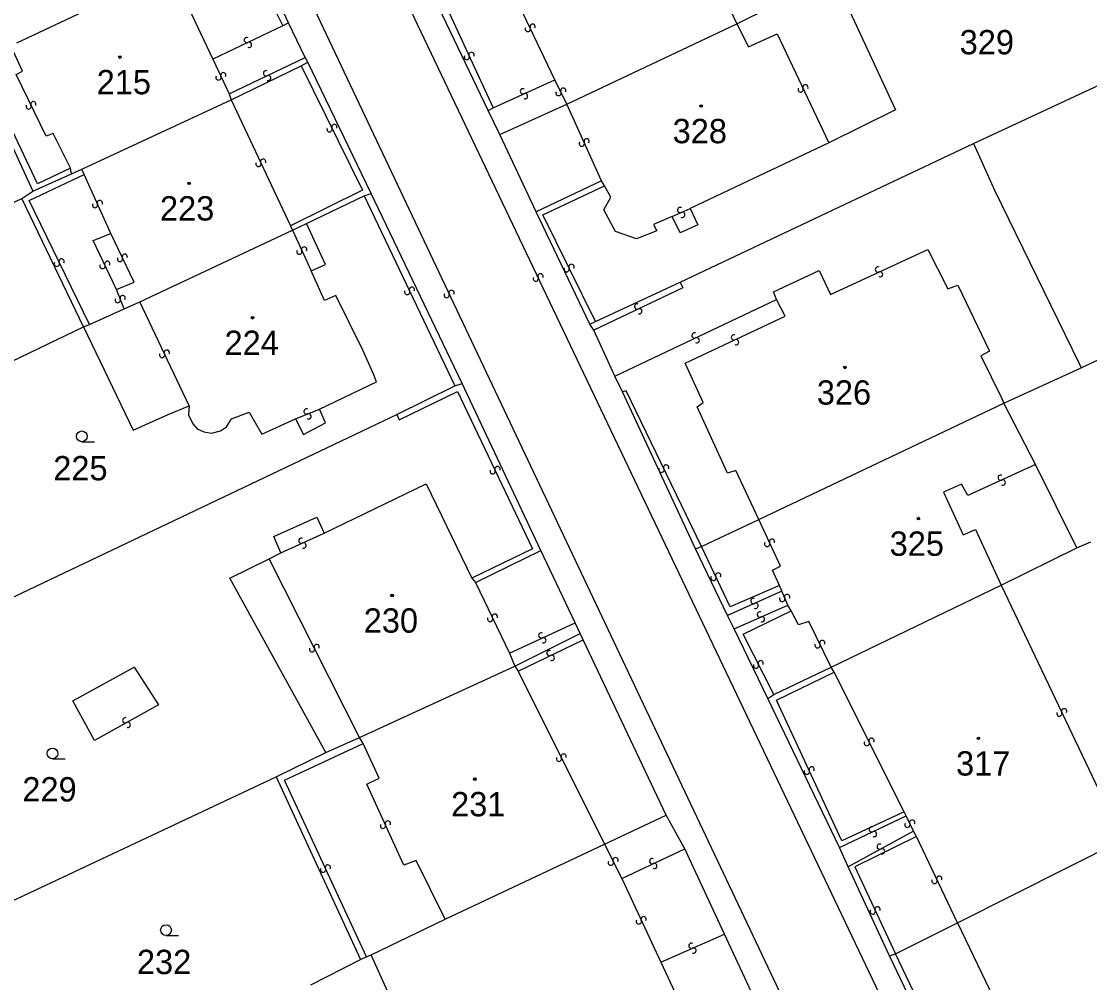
# Model space of a CAD drawing. Extents: x -600391 to -599491, y -1160176 to -1159402.
# Drawn here: x -600227.7 to -600153, y -1159801.1 to -1159733.9 of the extents above; entities that cross this region are included whole.
import ezdxf

# ---------------------------------------------------------------- set-up
doc = ezdxf.new("R2010")
doc.units = 0
for name, color, linetype in [('Level 1', 7, 'Continuous'), ('Level 13', 7, 'Continuous'), ('Level 3', 7, 'Continuous'), ('Level 4', 7, 'Continuous'), ('Level 5', 7, 'Continuous')]:
    doc.layers.add(name, color=color, linetype=linetype)

msp = doc.modelspace()

# ---------------------------------------------------------------- linework, layer by layer
at = {"layer": 'Level 1'}
for points in [[(-600208.99, -1159734.03), (-600211.94, -1159727.78)], [(-600227.96, -1159735.44), (-600217.22, -1159730.36)], [(-600171.01, -1159730.92), (-600170.82, -1159731.24), (-600169.15, -1159730.44), (-600168.52, -1159731.82), (-600170.09, -1159732.6), (-600166.61, -1159740.12), (-600171.26, -1159742.42)], [(-600195.05, -1159740.16), (-600198.5, -1159732.97)], [(-600177.67, -1159734.1), (-600175.23, -1159732.89)], [(-600207.83, -1159736.46), (-600208.99, -1159734.03)], [(-600189.55, -1159739.72), (-600177.67, -1159734.1)], [(-600161.16, -1159742.46), (-600146.3, -1159735.55)], [(-600207.65, -1159736.78), (-600207.83, -1159736.46)], [(-600230.94, -1159736.91), (-600226.86, -1159745.79)], [(-600213.01, -1159739.43), (-600208.1, -1159737.04)], [(-600208.1, -1159737.04), (-600207.65, -1159736.78)], [(-600203.22, -1159745.95), (-600207.65, -1159736.78)], [(-600223.43, -1159744.26), (-600213.01, -1159739.43)], [(-600194.23, -1159741.85), (-600195.05, -1159740.16)], [(-600194.23, -1159741.85), (-600189.55, -1159739.72)], [(-600191.69, -1159747.24), (-600194.23, -1159741.85)], [(-600181.63, -1159752.15), (-600161.16, -1159742.46)], [(-600171.26, -1159742.42), (-600180.94, -1159747)], [(-600161.16, -1159742.46), (-600159.69, -1159745.74), (-600153.77, -1159757.84), (-600153.64, -1159758.15)], [(-600226.86, -1159745.79), (-600224.16, -1159744.58)], [(-600224.16, -1159744.58), (-600223.43, -1159744.26)], [(-600187.13, -1159745.08), (-600191.69, -1159747.24)], [(-600186.92, -1159745.43), (-600187.13, -1159745.08)], [(-600182.2, -1159747.56), (-600183.5, -1159748.12), (-600183.27, -1159748.58), (-600184.69, -1159749.12), (-600186.16, -1159748.61), (-600186.98, -1159747.11), (-600186.48, -1159746.21), (-600186.92, -1159745.43)], [(-600227.63, -1159746.31), (-600226.86, -1159745.79)], [(-600207.73, -1159748.06), (-600203.71, -1159746.12)], [(-600203.71, -1159746.12), (-600203.22, -1159745.95)], [(-600196.87, -1159759.24), (-600203.22, -1159745.95)], [(-600251.26, -1159757.45), (-600227.63, -1159746.31)], [(-600223.31, -1159755.28), (-600227.63, -1159746.31)], [(-600187.96, -1159755.09), (-600191.69, -1159747.24)], [(-600180.94, -1159747), (-600180.41, -1159748.14), (-600181.63, -1159748.71), (-600182.2, -1159747.56)], [(-600208.72, -1159748.53), (-600207.73, -1159748.06)], [(-600207.42, -1159751.37), (-600206.42, -1159750.91), (-600207.73, -1159748.06)], [(-600219.39, -1159753.54), (-600208.72, -1159748.53)], [(-600206.84, -1159761.02), (-600202.85, -1159759.11), (-600203.04, -1159758.62), (-600203.78, -1159756.95), (-600205.68, -1159753.09), (-600206.48, -1159753.43), (-600207.42, -1159751.37)], [(-600153.64, -1159758.15), (-600138, -1159750.77)], [(-600187.56, -1159754.91), (-600181.63, -1159752.15)], [(-600220.48, -1159754.01), (-600219.39, -1159753.54)], [(-600222.9, -1159755.12), (-600220.48, -1159754.01)], [(-600223.31, -1159755.28), (-600222.9, -1159755.12)], [(-600187.96, -1159755.09), (-600187.56, -1159754.91)], [(-600187.68, -1159755.5), (-600187.96, -1159755.09)], [(-600246.59, -1159766.48), (-600223.31, -1159755.28)], [(-600223.31, -1159755.28), (-600219.85, -1159762.49), (-600217.41, -1159761.4), (-600215.93, -1159760.79)], [(-600186.2, -1159758.73), (-600187.68, -1159755.5)], [(-600185.67, -1159759.81), (-600186.2, -1159758.73)], [(-600159.03, -1159760.61), (-600153.64, -1159758.15)], [(-600201.43, -1159761.41), (-600197.38, -1159759.4)], [(-600197.38, -1159759.4), (-600196.87, -1159759.24)], [(-600191.36, -1159770.9), (-600196.87, -1159759.24)], [(-600180.56, -1159770.78), (-600185.67, -1159759.81)], [(-600215.93, -1159760.79), (-600215.97, -1159761.42), (-600215.67, -1159762.05), (-600215.37, -1159762.39), (-600214.9, -1159762.61), (-600214.38, -1159762.7), (-600213.75, -1159762.55), (-600213.33, -1159762.25), (-600212.97, -1159761.71), (-600211.75, -1159761.23), (-600210.85, -1159762.78), (-600208.5, -1159761.69)], [(-600208.5, -1159761.69), (-600207.94, -1159762.79), (-600206.4, -1159761.99), (-600206.84, -1159761.02)], [(-600176.14, -1159768.74), (-600159.03, -1159760.61)], [(-600156.81, -1159764.9), (-600159.03, -1159760.61)], [(-600239.75, -1159779.63), (-600201.43, -1159761.41)], [(-600153.94, -1159770.71), (-600156.81, -1159764.9)], [(-600206.51, -1159769.68), (-600199.39, -1159766.24), (-600196.2, -1159772.82)], [(-600209.53, -1159771.07), (-600210.02, -1159769.92), (-600207.02, -1159768.56), (-600206.51, -1159769.68)], [(-600180.16, -1159770.62), (-600176.14, -1159768.74)], [(-600180.56, -1159770.78), (-600180.16, -1159770.62)], [(-600178.34, -1159775.45), (-600180.56, -1159770.78)], [(-600159.23, -1159773.32), (-600153.94, -1159770.71)], [(-600153.94, -1159770.71), (-600152.96, -1159770.3)], [(-600206.39, -1159785), (-600213.09, -1159772.84), (-600210.34, -1159771.48)], [(-600210.34, -1159771.48), (-600209.53, -1159771.07)], [(-600195.93, -1159773.14), (-600191.36, -1159770.9)], [(-600188.97, -1159775.94), (-600191.36, -1159770.9)], [(-600196.2, -1159772.82), (-600195.93, -1159773.14)], [(-600171.1, -1159779.04), (-600159.23, -1159773.32)], [(-600188.62, -1159776.69), (-600188.97, -1159775.94)], [(-600177.86, -1159776.38), (-600178.34, -1159775.45)], [(-600193.19, -1159778.98), (-600188.62, -1159776.69)], [(-600188.41, -1159777.13), (-600188.62, -1159776.69)], [(-600175.52, -1159781.23), (-600177.86, -1159776.38)], [(-600182.61, -1159789.39), (-600188.41, -1159777.13)], [(-600204.03, -1159783.96), (-600193.19, -1159778.98)], [(-600175.1, -1159780.96), (-600171.1, -1159779.04)], [(-600175.52, -1159781.23), (-600175.1, -1159780.96)], [(-600170.5, -1159791.65), (-600175.52, -1159781.23)], [(-600206.39, -1159785), (-600204.03, -1159783.96)], [(-600209.86, -1159786.71), (-600206.39, -1159785)], [(-600231.06, -1159796.68), (-600209.86, -1159786.71)], [(-600209.86, -1159786.71), (-600203.96, -1159799.47)], [(-600186.92, -1159791.42), (-600182.61, -1159789.39)], [(-600181.31, -1159791.73), (-600182.61, -1159789.39)], [(-600198.05, -1159796.66), (-600186.92, -1159791.42)], [(-600169.9, -1159792.99), (-600170.5, -1159791.65)], [(-600162.28, -1159796.91), (-600150.75, -1159791.1)], [(-600178.55, -1159797.71), (-600181.31, -1159791.73)], [(-600167.03, -1159799.22), (-600169.9, -1159792.99)], [(-600203.22, -1159799.15), (-600198.05, -1159796.66)], [(-600166.61, -1159799.07), (-600162.28, -1159796.91)], [(-600162.28, -1159796.91), (-600156.73, -1159808.45), (-600157.7, -1159809.01), (-600154.94, -1159814.73), (-600143.87, -1159808.62)], [(-600175.73, -1159803.75), (-600178.55, -1159797.71)], [(-600203.54, -1159799.29), (-600203.22, -1159799.15)], [(-600167.03, -1159799.22), (-600166.61, -1159799.07)], [(-600207.44, -1159801.23), (-600203.96, -1159799.47)], [(-600203.96, -1159799.47), (-600203.54, -1159799.29)], [(-600156.4, -1159821.41), (-600167.03, -1159799.22)]]:
    msp.add_lwpolyline(points, dxfattribs=at)
at = {"layer": 'Level 13'}
for centre, start, end in [((-600191.943, -1159734.312), 332.57245, 205.16245), ((-600192.277, -1159734.468), 152.78691, 24.88491), ((-600211.908, -1159735.243), 62.4944, 295.0844), ((-600211.753, -1159735.577), 242.70886, 114.80685), ((-600196.547, -1159736.437), 152.01879, 24.60879), ((-600196.212, -1159736.284), 332.23325, 204.33124), ((-600213.887, -1159737.857), 152.18813, 24.77813), ((-600213.552, -1159737.704), 332.40259, 204.50058), ((-600210.568, -1159737.563), 62.80681, 294.90481), ((-600210.412, -1159737.897), 242.59235, 115.18235), ((-600192.625, -1159738.821), 61.8267, 293.9247), ((-600189.804, -1159738.78), 333.31984, 205.90984), ((-600173.227, -1159738.698), 152.47532, 25.06532), ((-600172.893, -1159738.543), 332.68978, 204.78777), ((-600192.475, -1159739.158), 241.61225, 114.20225), ((-600190.136, -1159738.94), 153.5343, 25.6323), ((-600227.147, -1159739.879), 153.29464, 25.39264), ((-600226.814, -1159739.72), 333.08019, 205.67019), ((-600206.126, -1159741.47), 153.30029, 25.89029), ((-600205.794, -1159741.31), 333.51475, 205.61275), ((-600188.509, -1159742.474), 151.67155, 23.76955), ((-600188.172, -1159742.325), 331.4571, 204.0471), ((-600211.097, -1159743.898), 152.48484, 25.07484), ((-600210.763, -1159743.743), 332.69929, 204.79729), ((-600222.509, -1159746.774), 151.50234, 23.60034), ((-600222.172, -1159746.625), 331.28788, 203.87788), ((-600181.643, -1159747.111), 61.33522, 293.43322), ((-600181.496, -1159747.449), 241.12077, 113.71077), ((-600208.238, -1159750.026), 151.75405, 24.34405), ((-600207.902, -1159749.875), 331.96851, 204.0665), ((-600224.844, -1159750.71), 333.11213, 205.70213), ((-600220.767, -1159750.538), 152.98634, 25.08434), ((-600220.434, -1159750.381), 332.77189, 205.36189), ((-600225.177, -1159750.869), 153.32658, 25.42458), ((-600221.988, -1159751.027), 152.58193, 24.67992), ((-600221.653, -1159750.872), 332.36747, 204.95747), ((-600189.566, -1159751.25), 153.53755, 25.63555), ((-600189.234, -1159751.09), 333.3231, 205.9131), ((-600167.826, -1159751.272), 62.15856, 294.25656), ((-600167.674, -1159751.607), 241.9441, 114.5341), ((-600191.727, -1159751.908), 152.84713, 24.94513), ((-600191.393, -1159751.752), 332.63268, 205.22268), ((-600200.706, -1159752.838), 152.64339, 25.23339), ((-600200.373, -1159752.682), 332.85785, 204.95584), ((-600197.613, -1159752.903), 332.70521, 204.80321), ((-600220.922, -1159753.407), 149.17414, 21.27214), ((-600220.579, -1159753.272), 328.95969, 201.54969), ((-600197.947, -1159753.058), 152.49075, 25.08075), ((-600184.648, -1159753.853), 62.49655, 295.08655), ((-600184.493, -1159754.187), 242.711, 114.809), ((-600180.638, -1159755.883), 62.76906, 294.86706), ((-600177.887, -1159756.012), 62.44345, 294.54145), ((-600180.482, -1159756.217), 242.55461, 115.14461), ((-600177.733, -1159756.347), 242.22899, 114.81899), ((-600217.827, -1159757.238), 152.88514, 24.98314), ((-600217.494, -1159757.081), 332.67069, 205.26069), ((-600207.737, -1159761.188), 59.35245, 291.45045), ((-600207.602, -1159761.531), 239.13799, 111.72799), ((-600194.736, -1159765.368), 152.64995, 25.23995), ((-600194.403, -1159765.212), 332.8644, 204.9624), ((-600182.947, -1159765.259), 153.13175, 25.22975), ((-600182.614, -1159765.101), 332.91729, 205.50729), ((-600159.256, -1159765.812), 61.65685, 294.24685), ((-600159.105, -1159766.149), 241.87131, 113.96931), ((-600208.096, -1159770.212), 62.08769, 294.18569), ((-600207.944, -1159770.548), 241.87323, 114.46323), ((-600175.558, -1159770.436), 152.14787, 24.24587), ((-600175.223, -1159770.284), 331.93342, 204.52342), ((-600179.317, -1159772.808), 152.95191, 25.04991), ((-600178.984, -1159772.651), 332.73746, 205.32746), ((-600176.525, -1159774.422), 61.56805, 294.15805), ((-600174.51, -1159774.291), 150.57133, 22.66932), ((-600174.171, -1159774.148), 330.35687, 202.94687), ((-600176.375, -1159774.759), 241.78251, 113.88051), ((-600176.074, -1159775.371), 61.49181, 293.5898), ((-600194.916, -1159775.679), 152.7388, 25.3288), ((-600194.583, -1159775.522), 332.95326, 205.05125), ((-600175.926, -1159775.708), 241.27735, 113.86735), ((-600191.346, -1159776.832), 62.21892, 294.31692), ((-600207.025, -1159777.638), 333.97985, 206.56985), ((-600191.193, -1159777.167), 242.00447, 114.59447), ((-600172.047, -1159777.519), 153.28754, 25.38554), ((-600171.714, -1159777.36), 333.07309, 205.66309), ((-600207.355, -1159777.802), 154.1943, 26.2923), ((-600190.768, -1159778.063), 63.07511, 295.17311), ((-600190.611, -1159778.396), 242.86066, 115.45066), ((-600176.345, -1159778.942), 154.42563, 26.52363), ((-600176.016, -1159778.777), 334.21117, 206.80117), ((-600154.823, -1159782.132), 332.87109, 204.96909), ((-600220.399, -1159782.759), 66.18022, 298.77022), ((-600155.156, -1159782.289), 152.65664, 25.24664), ((-600220.222, -1159783.082), 246.39468, 118.49268), ((-600168.275, -1159784.188), 333.81718, 206.40718), ((-600168.606, -1159784.351), 154.03164, 26.12963), ((-600190.105, -1159785.451), 153.68544, 26.27544), ((-600189.774, -1159785.289), 333.89989, 205.99789), ((-600172.788, -1159786.346), 152.21068, 24.30868), ((-600172.453, -1159786.193), 331.99622, 204.58622), ((-600202.399, -1159790.125), 151.87767, 23.97567), ((-600202.062, -1159789.974), 331.66322, 204.25322), ((-600168.258, -1159790.373), 62.79302, 294.89101), ((-600165.767, -1159790.058), 152.85686, 24.95486), ((-600165.434, -1159789.902), 332.64241, 205.23241), ((-600168.102, -1159790.707), 242.57856, 115.16856), ((-600167.707, -1159791.588), 65.69826, 298.28826), ((-600186.154, -1159792.539), 334.0336, 206.13159), ((-600183.597, -1159792.602), 62.62389, 294.72189), ((-600167.533, -1159791.913), 245.91272, 118.01072), ((-600206.578, -1159793.196), 152.31841, 24.41641), ((-600206.243, -1159793.043), 332.10396, 204.69396), ((-600186.485, -1159792.702), 153.81914, 26.40914), ((-600183.442, -1159792.937), 242.40944, 114.99944), ((-600163.877, -1159793.977), 152.66988, 24.76787), ((-600163.543, -1159793.822), 332.45542, 205.04542), ((-600168.187, -1159796.117), 152.07691, 24.66691), ((-600167.852, -1159795.964), 332.29137, 204.38936), ((-600184.527, -1159796.807), 152.09469, 24.68469), ((-600184.192, -1159796.654), 332.30915, 204.40714), ((-600180.852, -1159798.51), 61.03588, 293.13387), ((-600180.707, -1159798.849), 240.82142, 113.41142)]:
    msp.add_arc(centre, 0.184, start, end, dxfattribs=at)
at = {"layer": 'Level 3'}
for points in [[(-600154.85, -1159824.6), (-600155.7, -1159824.37), (-600156.33, -1159824.07), (-600156.83, -1159823.72), (-600157.25, -1159823.34), (-600157.63, -1159822.87), (-600158.01, -1159822.25), (-600225.11, -1159681.41), (-600225.5, -1159680.26), (-600225.71, -1159678.98), (-600225.76, -1159677.2), (-600225.55, -1159675.64)], [(-600236.3, -1159676.88), (-600235.69, -1159677.1), (-600234.79, -1159677.54), (-600233.86, -1159678.21), (-600233.01, -1159679.1), (-600232.25, -1159680.16), (-600163.31, -1159825.79), (-600162.94, -1159826.86), (-600162.86, -1159827.88), (-600163.01, -1159828.81), (-600163.4, -1159829.75)], [(-600183.7, -1159725.92), (-600181.9, -1159729.68), (-600180.2, -1159728.82), (-600177.67, -1159734.1)], [(-600212.49, -1159728.03), (-600209.38, -1159734.25)], [(-600217.22, -1159730.36), (-600214.28, -1159736.57)], [(-600190.39, -1159738.01), (-600193.83, -1159730.77)], [(-600198.05, -1159732.74), (-600194.7, -1159739.97)], [(-600209.38, -1159734.25), (-600214.28, -1159736.57)], [(-600208.99, -1159734.03), (-600209.38, -1159734.25)], [(-600177.67, -1159734.1), (-600176.87, -1159735.72), (-600174.86, -1159734.81), (-600171.26, -1159742.42)], [(-600224.23, -1159744.2), (-600225.44, -1159741.77), (-600225.93, -1159741.95), (-600228.02, -1159737.65), (-600227.57, -1159737.41), (-600228.36, -1159735.69)], [(-600213.15, -1159738.99), (-600207.83, -1159736.46)], [(-600224.23, -1159744.2), (-600226.52, -1159745.29), (-600230.58, -1159736.74)], [(-600214.28, -1159736.57), (-600213.15, -1159738.99)], [(-600208.1, -1159737.04), (-600203.83, -1159745.74), (-600208.85, -1159748.22)], [(-600194.7, -1159739.97), (-600190.39, -1159738.01)], [(-600189.55, -1159739.72), (-600190.39, -1159738.01)], [(-600213.15, -1159738.99), (-600213.01, -1159739.43)], [(-600213.01, -1159739.43), (-600208.85, -1159748.22)], [(-600195.05, -1159740.16), (-600194.7, -1159739.97)], [(-600187.13, -1159745.08), (-600189.55, -1159739.72)], [(-600222.9, -1159755.12), (-600227.12, -1159746.45), (-600223.26, -1159744.63)], [(-600224.16, -1159744.58), (-600224.23, -1159744.2)], [(-600223.26, -1159744.63), (-600223.43, -1159744.26)], [(-600221.41, -1159748.76), (-600223.26, -1159744.63)], [(-600187.56, -1159754.91), (-600191.23, -1159747.44), (-600186.92, -1159745.43)], [(-600203.71, -1159746.12), (-600197.38, -1159759.4)], [(-600182.2, -1159747.56), (-600180.94, -1159747)], [(-600208.85, -1159748.22), (-600208.72, -1159748.53)], [(-600221.02, -1159752.66), (-600222.63, -1159749.24), (-600221.41, -1159748.76)], [(-600221.02, -1159752.66), (-600219.78, -1159752.16), (-600221.41, -1159748.76)], [(-600208.72, -1159748.53), (-600207.42, -1159751.37)], [(-600174.91, -1159753.37), (-600175.13, -1159752.84), (-600171.94, -1159751.34), (-600171.15, -1159753.01), (-600164.35, -1159749.87), (-600162.94, -1159752.61), (-600162.24, -1159752.36), (-600160.03, -1159756.98), (-600160.65, -1159757.29), (-600159.17, -1159760.27), (-600159.03, -1159760.61)], [(-600181.63, -1159752.15), (-600181.45, -1159752.55), (-600187.68, -1159755.5)], [(-600220.48, -1159754.01), (-600221.02, -1159752.66)], [(-600215.93, -1159760.79), (-600219.39, -1159753.54)], [(-600186.2, -1159758.73), (-600174.91, -1159753.37)], [(-600176.14, -1159768.74), (-600177.74, -1159765.32), (-600178.34, -1159765.5), (-600180.46, -1159760.87), (-600180.03, -1159760.57), (-600181.3, -1159757.81), (-600174.31, -1159754.54), (-600174.91, -1159753.37)], [(-600201.43, -1159761.41), (-600201.26, -1159761.77), (-600197.19, -1159759.79), (-600191.95, -1159770.78), (-600196.2, -1159772.82)], [(-600180.16, -1159770.62), (-600185.41, -1159759.74), (-600185.67, -1159759.81)], [(-600208.5, -1159761.69), (-600206.84, -1159761.02)], [(-600156.81, -1159764.9), (-600161.55, -1159767.06), (-600161.99, -1159766.26), (-600163.24, -1159766.82), (-600161.88, -1159769.81), (-600161.01, -1159769.43), (-600159.23, -1159773.32)], [(-600174.71, -1159773.34), (-600175.2, -1159772.28), (-600174.64, -1159771.99), (-600176.14, -1159768.74)], [(-600209.53, -1159771.07), (-600206.51, -1159769.68)], [(-600174.71, -1159773.34), (-600178.14, -1159774.84), (-600180.16, -1159770.62)], [(-600204.03, -1159783.96), (-600210.34, -1159771.48)], [(-600195.93, -1159773.14), (-600193.57, -1159778.07)], [(-600174.55, -1159773.73), (-600178.34, -1159775.45)], [(-600174.55, -1159773.73), (-600174.71, -1159773.34)], [(-600174.13, -1159774.71), (-600174.55, -1159773.73)], [(-600159.23, -1159773.32), (-600150.75, -1159791.1)], [(-600177.86, -1159776.38), (-600174.13, -1159774.71)], [(-600175.1, -1159780.96), (-600177.25, -1159776.75), (-600173.88, -1159775.11)], [(-600173.88, -1159775.11), (-600174.13, -1159774.71)], [(-600171.1, -1159779.04), (-600172.65, -1159775.85), (-600173.38, -1159776.1), (-600173.88, -1159775.11)], [(-600193.57, -1159778.07), (-600188.97, -1159775.94)], [(-600192.96, -1159779.32), (-600188.41, -1159777.13)], [(-600193.57, -1159778.07), (-600193.19, -1159778.98)], [(-600193.19, -1159778.98), (-600192.96, -1159779.32)], [(-600218.08, -1159781.68), (-600222.55, -1159784.16), (-600224.06, -1159781.39), (-600219.78, -1159779.05), (-600218.08, -1159781.68)], [(-600192.96, -1159779.32), (-600186.92, -1159791.42)], [(-600165.99, -1159789.15), (-600170.35, -1159791.19), (-600174.9, -1159781.36), (-600170.89, -1159779.39)], [(-600170.89, -1159779.39), (-600171.1, -1159779.04)], [(-600165.99, -1159789.15), (-600170.89, -1159779.39)], [(-600203.77, -1159784.37), (-600204.03, -1159783.96)], [(-600203.54, -1159799.29), (-600209.28, -1159786.95), (-600203.77, -1159784.37)], [(-600198.05, -1159796.66), (-600200.09, -1159792.55), (-600200.94, -1159792.88), (-600203.52, -1159787.22), (-600202.67, -1159786.81), (-600203.77, -1159784.37)], [(-600170.5, -1159791.65), (-600165.85, -1159789.44)], [(-600165.85, -1159789.44), (-600165.99, -1159789.15)], [(-600165.34, -1159790.51), (-600165.85, -1159789.44)], [(-600165.34, -1159790.51), (-600169.9, -1159792.99)], [(-600165.13, -1159790.88), (-600169.43, -1159793), (-600166.61, -1159799.07)], [(-600165.13, -1159790.88), (-600165.34, -1159790.51)], [(-600162.28, -1159796.91), (-600165.13, -1159790.88)], [(-600186.92, -1159791.42), (-600185.72, -1159793.81)], [(-600185.72, -1159793.81), (-600181.31, -1159791.73)], [(-600185.72, -1159793.81), (-600183, -1159799.66)], [(-600183, -1159799.66), (-600178.55, -1159797.71)], [(-600192.58, -1159811.78), (-600192.81, -1159811.33), (-600194.39, -1159808.23), (-600196.59, -1159809.23), (-600198.88, -1159804.48), (-600200.52, -1159805.15), (-600203.22, -1159799.15)], [(-600143.87, -1159808.62), (-600141.69, -1159812.83), (-600156.27, -1159820.7), (-600166.61, -1159799.07)], [(-600183, -1159799.66), (-600180.1, -1159805.85)]]:
    msp.add_lwpolyline(points, dxfattribs=at)
at = {"layer": 'Level 5'}
for p, q in [((-600223.43, -1159763.3), (-600222.555, -1159763.3)), ((-600225.48, -1159785.45), (-600224.605, -1159785.45)), ((-600217.55, -1159797.79), (-600216.675, -1159797.79))]:
    msp.add_line(p, q, dxfattribs=at)
for centre, radius in [((-600220.77, -1159736.43), 0.09), ((-600220.77, -1159736.43), 0.0521), ((-600180.17, -1159739.85), 0.09), ((-600180.17, -1159739.85), 0.0521), ((-600215.94, -1159745.25), 0.09), ((-600215.94, -1159745.25), 0.0521), ((-600211.51, -1159754.64), 0.09), ((-600211.51, -1159754.64), 0.0521), ((-600170.13, -1159758.11), 0.09), ((-600170.13, -1159758.11), 0.0521), ((-600223.43, -1159762.925), 0.375), ((-600165, -1159768.67), 0.09), ((-600165, -1159768.67), 0.0521), ((-600201.75, -1159774.04), 0.09), ((-600201.75, -1159774.04), 0.0521), ((-600160.81, -1159784.02), 0.09), ((-600160.81, -1159784.02), 0.0521), ((-600225.48, -1159785.075), 0.375), ((-600195.98, -1159786.87), 0.09), ((-600195.98, -1159786.87), 0.0521), ((-600217.55, -1159797.415), 0.375)]:
    msp.add_circle(centre, radius, dxfattribs=at)

# ---------------------------------------------------------------- texts
at = {"layer": 'Level 4'}
for s, p in [('329', (-600162.116, -1159736.24)), ('215', (-600222.394, -1159739.03)), ('328', (-600182.164, -1159742.45)), ('223', (-600217.971, -1159747.85)), ('224', (-600213.464, -1159757.24)), ('326', (-600172.096, -1159760.71)), ('225', (-600225.426, -1159766)), ('325', (-600167.007, -1159771.27)), ('230', (-600203.74, -1159776.64)), ('317', (-600162.369, -1159786.62)), ('229', (-600227.584, -1159788.43)), ('231', (-600197.639, -1159789.47)), ('232', (-600219.581, -1159800.49))]:
    msp.add_text(s, height=1.7, dxfattribs=at).set_placement(p)

doc.saveas('drawing.dxf')
